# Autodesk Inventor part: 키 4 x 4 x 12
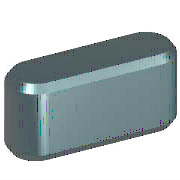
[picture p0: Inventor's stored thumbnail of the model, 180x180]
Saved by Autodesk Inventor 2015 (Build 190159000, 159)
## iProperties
IsCustomPart: 1
Created: 2012-02
Part Number: 키 4 x 4 x 12
Material: 강철, 연강
Description: 키 및 해당 키홈
Document SubType Name: Modeling
Standard: KS B 1311
Designer: mduedu
Standards Organization: KS
Language: ko-KR
Size Designation: 4 x 4 x 12
Categories: <MemberInstance><Categories><Category DisplayName="샤프트 부품" InternalName="7f7aeb1f-a693-4053-b835-cee3144e0d98" Mnemonic="SHFT"><Category DisplayName="키" Interna
Density: 1 g/cm^3
Appearance: 노란색
Author: mduedu
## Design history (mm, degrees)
workplane "Work Plane1"
workplane "Work Plane2"
sketch "스케치1"
  geometry: L1 (2, 2)-(10, 2); L2 (10, -2)-(2, -2); L3 (0, 9.4)-(0, -7.4) reference; L4 (-5, 0)-(30, 0) reference; L5 (12, 0)-(12, 7); A1 r 2 centre (2, 0) between (2, 2) and (2, -2); A2 r 2 centre (10, 0) between (10, -2) and (10, 2)
  constraints: 6 end point, 5 point on circle, 4 tangent, 3 point on line, 2 centre point, 1 horizontal, 1 parallel, 1 perpendicular
  dimensions: "d0" = 2 radius of A1 (= 0.5 x PB); "d13" = 2 radius of A2 (= 0.5 x PB); "d14" = 12 distance between parallel lines of L5 L3 (= NLG)
extrude "본체1" new body sketch "스케치1" taper "d3" = 0 deg; stored distance "d4" = 10
workplane "Work Plane3"
body "Solid1"
chamfer "모따기1" distance "d8" = 0.25 (= PHH); stored, may be unused: second distance "d9" = 0.25 (= PHH), angle "d15" = 45 deg
other parameters: "d1" = -2.5 (= -PNT), "d2" = 1.5 (= PH - PNT), "NLG" = 12 [user parameter; used in 3 equation terms], "PB" = 4 [user parameter; used in 2 equation terms], "PNT" = 2.5 [user parameter; used in 2 equation terms], "PH" = 4 [user parameter; used in 1 equation term], "PHH" = 0.25 [user parameter; used in 2 equation terms], "d10" = 0, "d16" = 0, "d17" = 0, "d18" = 0, "PLB2" = 12 (= NLG) [user parameter], "WDMAX" = 12 [user parameter], "PLB1" = 12 (= NLG) [user parameter], "RR" = 0.08 [user parameter], "PUEB" = 1.8 [user parameter]
